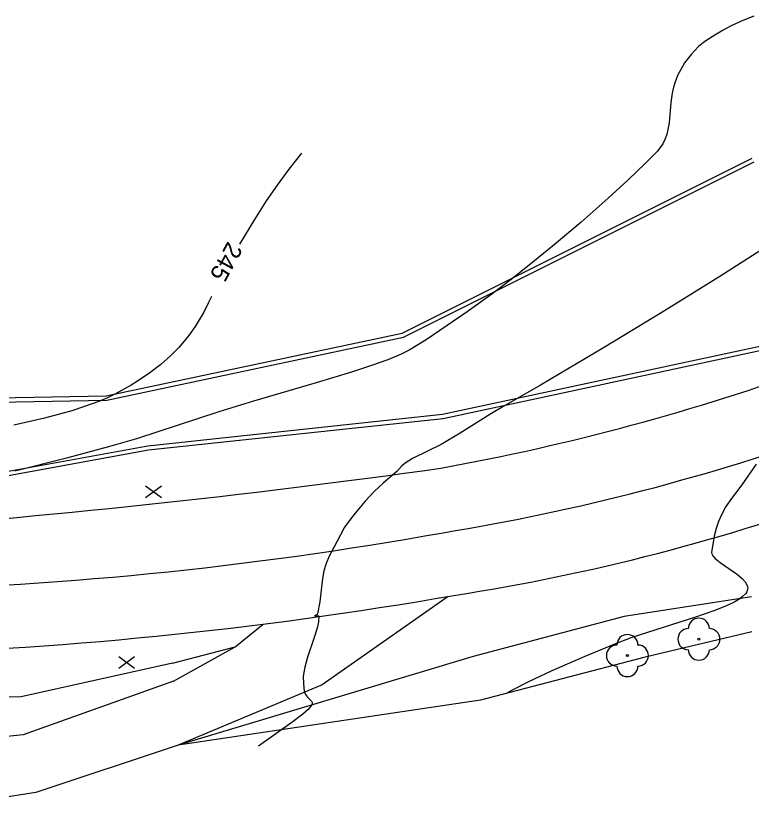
# Model space of a CAD drawing. Extents: x -593772 to -592667, y -1183541 to -1183371.
# Drawn here: x -592789.06 to -592754.06, y -1183536.62 to -1183498.5 of the extents above; entities that cross this region are included whole.
import ezdxf

# ---------------------------------------------------------------- set-up
doc = ezdxf.new("R2010")
doc.units = 0
for name, color, linetype in [('bez obruby', 7, 'Continuous'), ('hlavni vrstevnice', 7, 'Continuous'), ('rozhrani ploch', 7, 'Continuous'), ('svisle dopravni znaceni', 7, 'Continuous'), ('terenni hrany', 7, 'Continuous'), ('vodorovne dopravni znaceni', 7, 'Continuous'), ('vrstevnice', 7, 'Continuous'), ('zelen', 7, 'Continuous')]:
    doc.layers.add(name, color=color, linetype=linetype)

msp = doc.modelspace()

# ---------------------------------------------------------------- linework, layer by layer
at = {"layer": 'bez obruby'}
for centre, radius, start, end in [((-592788.634, -1183411.087), 110.686, 280.29638, 289.90486), ((-592827.441, -1183102.991), 421.095, 274.15372, 277.99806), ((-592783.311, -1183428.474), 98.723, 278.78098, 290.27546), ((-592801.596, -1183335.219), 193.714, 271.46599, 279.91525)]:
    msp.add_arc(centre, radius, start, end, dxfattribs=at)
at = {"layer": 'hlavni vrstevnice'}
for points in [[(-592775.483, -1183505.011), (-592776.089, -1183505.776), (-592776.641, -1183506.532), (-592777.155, -1183507.289), (-592777.714, -1183508.173), (-592778.423, -1183509.346)], [(-592779.77, -1183511.828), (-592779.917, -1183512.144), (-592780.133, -1183512.568), (-592780.39, -1183513.019), (-592780.539, -1183513.255), (-592780.811, -1183513.642), (-592781.055, -1183513.952), (-592781.314, -1183514.249), (-592781.712, -1183514.653), (-592782.17, -1183515.056), (-592782.697, -1183515.461), (-592783.284, -1183515.858), (-592783.588, -1183516.046), (-592784.325, -1183516.462), (-592784.708, -1183516.646), (-592785.116, -1183516.818), (-592785.804, -1183517.066), (-592786.407, -1183517.258), (-592787.704, -1183517.61), (-592789.161, -1183517.951)]]:
    msp.add_lwpolyline(points, dxfattribs=at)
at = {"layer": 'rozhrani ploch'}
for p, q in [((-592768.512, -1183526.087), (-592774.5, -1183530.29)), ((-592778.64, -1183528.48), (-592777.3, -1183527.404)), ((-592774.5, -1183530.29), (-592781.35, -1183533.16)), ((-592781.35, -1183533.16), (-592788.11, -1183535.41)), ((-592788.11, -1183535.41), (-592796.07, -1183536.62))]:
    msp.add_line(p, q, dxfattribs=at)
at = {"layer": 'svisle dopravni znaceni'}
for p, q in [((-592782.895, -1183521.391), (-592782.145, -1183520.829)), ((-592782.895, -1183520.829), (-592782.145, -1183521.391)), ((-592784.175, -1183529.501), (-592783.425, -1183528.938)), ((-592784.175, -1183528.938), (-592783.425, -1183529.501))]:
    msp.add_line(p, q, dxfattribs=at)
at = {"layer": 'terenni hrany'}
for p, q in [((-592770.7, -1183513.58), (-592754.05, -1183505.25)), ((-592784.77, -1183516.56), (-592770.7, -1183513.58)), ((-592750.72, -1183513.77), (-592768.74, -1183517.64)), ((-592801.57, -1183516.85), (-592784.77, -1183516.56)), ((-592768.74, -1183517.64), (-592782.76, -1183519.14)), ((-592782.76, -1183519.14), (-592796.92, -1183521.72)), ((-592754.08, -1183526.1), (-592760.14, -1183527.05)), ((-592760.14, -1183527.05), (-592767.31, -1183528.95)), ((-592754.06, -1183527.77), (-592759.2, -1183528.99)), ((-592781.61, -1183529.26), (-592778.64, -1183528.48)), ((-592781.57, -1183530.11), (-592778.64, -1183528.48)), ((-592767.31, -1183528.95), (-592781.35, -1183533.16)), ((-592759.2, -1183528.99), (-592766.97, -1183531.02)), ((-592781.61, -1183529.26), (-592788.82, -1183530.86)), ((-592781.57, -1183530.11), (-592788.72, -1183532.67)), ((-592788.82, -1183530.86), (-592796.53, -1183531.01)), ((-592766.97, -1183531.02), (-592781.35, -1183533.16)), ((-592788.72, -1183532.67), (-592796.31, -1183533.45))]:
    msp.add_line(p, q, dxfattribs=at)
at = {"layer": 'vodorovne dopravni znaceni'}
for centre, radius, start, end in [((-592785.787, -1183418.791), 105.652, 279.27956, 289.81054), ((-592800.386, -1183346.795), 179.082, 271.15701, 280.17509)]:
    msp.add_arc(centre, radius, start, end, dxfattribs=at)
at = {"layer": 'vrstevnice'}
for points in [[(-592753.963, -1183498.498), (-592754.491, -1183498.703), (-592755.042, -1183498.96), (-592755.432, -1183499.168), (-592755.829, -1183499.402), (-592756.242, -1183499.677), (-592756.433, -1183499.82), (-592756.592, -1183499.952), (-592756.95, -1183500.32), (-592757.264, -1183500.73), (-592757.461, -1183501.063), (-592757.58, -1183501.297), (-592757.705, -1183501.621), (-592757.785, -1183501.879), (-592757.846, -1183502.165), (-592757.91, -1183502.604), (-592757.997, -1183503.569), (-592758.05, -1183503.884), (-592758.104, -1183504.106), (-592758.181, -1183504.332), (-592758.295, -1183504.566), (-592758.467, -1183504.814), (-592758.552, -1183504.917), (-592759.131, -1183505.515), (-592759.953, -1183506.299), (-592760.892, -1183507.154), (-592762.182, -1183508.29), (-592763.458, -1183509.371), (-592764.727, -1183510.406), (-592765.512, -1183511.027), (-592766.423, -1183511.713), (-592767.595, -1183512.554), (-592768.548, -1183513.21), (-592769.557, -1183513.884), (-592770.357, -1183514.383), (-592770.738, -1183514.573), (-592771.378, -1183514.836), (-592772.145, -1183515.113), (-592773.105, -1183515.429), (-592774.791, -1183515.937), (-592777.757, -1183516.799), (-592779.421, -1183517.317), (-592783.337, -1183518.599), (-592784.665, -1183518.983), (-592786.657, -1183519.52), (-592789.115, -1183520.141)], [(-592752.686, -1183509.026), (-592755.579, -1183510.872), (-592758.219, -1183512.514), (-592761.124, -1183514.274), (-592764.12, -1183516.043), (-592765.852, -1183517.042), (-592766.527, -1183517.444), (-592767.931, -1183518.334), (-592768.844, -1183518.863), (-592770.197, -1183519.532), (-592770.509, -1183519.714), (-592770.71, -1183519.877), (-592770.949, -1183520.142), (-592771.603, -1183520.698), (-592772.028, -1183521.101), (-592772.461, -1183521.567), (-592772.928, -1183522.135), (-592773.312, -1183522.625), (-592773.45, -1183522.823), (-592773.634, -1183523.157), (-592773.947, -1183523.766), (-592774.166, -1183524.173), (-592774.315, -1183524.525), (-592774.42, -1183524.864), (-592774.488, -1183525.243), (-592774.614, -1183526.343), (-592774.722, -1183526.909), (-592774.73, -1183526.942), (-592774.858, -1183527.006), (-592774.819, -1183527.017), (-592774.651, -1183527.013), (-592774.672, -1183527.289), (-592774.738, -1183527.603), (-592774.888, -1183528.09), (-592775.192, -1183528.979), (-592775.32, -1183529.455), (-592775.391, -1183529.782), (-592775.395, -1183529.927), (-592775.366, -1183530.459), (-592775.339, -1183530.646), (-592775.295, -1183530.752), (-592775.201, -1183530.872), (-592775.01, -1183531.065), (-592774.976, -1183531.131), (-592774.972, -1183531.184), (-592774.994, -1183531.243), (-592775.171, -1183531.457), (-592775.425, -1183531.69), (-592775.872, -1183532.04), (-592777.526, -1183533.212)], [(-592753.855, -1183519.794), (-592754.539, -1183520.786), (-592755.032, -1183521.426), (-592755.291, -1183521.821), (-592755.507, -1183522.212), (-592755.651, -1183522.532), (-592755.765, -1183522.86), (-592755.848, -1183523.23), (-592755.977, -1183523.994), (-592755.965, -1183524.069), (-592755.921, -1183524.157), (-592755.806, -1183524.289), (-592755.572, -1183524.481), (-592754.743, -1183525.051), (-592754.512, -1183525.245), (-592754.377, -1183525.394), (-592754.293, -1183525.534), (-592754.259, -1183525.662), (-592754.262, -1183525.766), (-592754.297, -1183525.867), (-592754.349, -1183525.952), (-592754.5, -1183526.099), (-592754.636, -1183526.205), (-592754.875, -1183526.349), (-592755.273, -1183526.537), (-592755.875, -1183526.775), (-592756.789, -1183527.092), (-592759.765, -1183528.036), (-592760.553, -1183528.339), (-592762.004, -1183528.94), (-592763.575, -1183529.629), (-592764.68, -1183530.147), (-592765.466, -1183530.55), (-592765.717, -1183530.693)]]:
    msp.add_lwpolyline(points, dxfattribs=at)
at = {"layer": 'zelen'}
for p, q in [((-592770.633, -1183513.77), (-592753.955, -1183505.426)), ((-592750.79, -1183513.581), (-592768.772, -1183517.442)), ((-592784.747, -1183516.76), (-592770.633, -1183513.77)), ((-592801.567, -1183517.05), (-592784.747, -1183516.76)), ((-592768.772, -1183517.442), (-592782.789, -1183518.942)), ((-592782.789, -1183518.942), (-592796.944, -1183521.521))]:
    msp.add_line(p, q, dxfattribs=at)
for centre in [(-592756.58, -1183528.12), (-592759.98, -1183528.9)]:
    msp.add_circle(centre, 0.05, dxfattribs=at)
for centre, start, end in [((-592756.58, -1183527.62), 0, 180), ((-592757.08, -1183528.12), 90, 270), ((-592756.08, -1183528.12), 270, 90), ((-592759.98, -1183528.4), 0, 180), ((-592760.48, -1183528.9), 90, 270), ((-592759.48, -1183528.9), 270, 90), ((-592756.58, -1183528.62), 180, 0), ((-592759.98, -1183529.4), 180, 0)]:
    msp.add_arc(centre, 0.5, start, end, dxfattribs=at)

# ---------------------------------------------------------------- texts
at = {"layer": 'hlavni vrstevnice'}
msp.add_text('245', height=0.8351, rotation=241.4704, dxfattribs=at).set_placement((-592778.981, -1183509.172))

doc.saveas('drawing.dxf')
